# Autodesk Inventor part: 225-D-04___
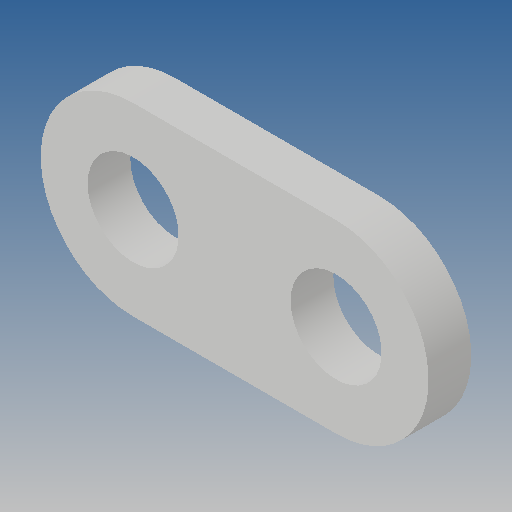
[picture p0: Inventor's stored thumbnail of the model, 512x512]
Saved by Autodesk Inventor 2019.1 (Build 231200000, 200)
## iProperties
Created: 2010-06
Part Number: 225-D-04___
Material: Ogólny
Document SubType Name: Modeling
Designer: CADENGINEERING4
Density: 1 g/cm^3
Appearance: Domyślna
Author: CADENGINEERING4
Revision Number: ANY
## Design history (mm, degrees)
feature "NONE"
node "Bryła1"
